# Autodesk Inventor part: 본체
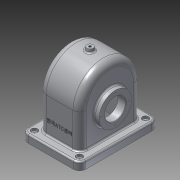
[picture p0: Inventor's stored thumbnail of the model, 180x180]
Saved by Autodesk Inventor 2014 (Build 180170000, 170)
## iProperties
Created: 2016-10
Part Number: 본체
Material: 알루미늄 6061
Document SubType Name: Modeling
Designer: user
Density: 2.71 g/cm^3
Appearance: 알루미늄 - 평지
Mass: 1165.05 g
Surface Area: 1200.06 cm^2
Volume: 429.908 cm^3
Author: user
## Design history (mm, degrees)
sketch "스케치1"
  geometry: L1 (-55, -75)-(55, -75); L2 (55, -75)-(55, 75); L3 (55, 75)-(-55, 75); L4 (-55, 75)-(-55, -75); L5 (-55, -75)-(55, 75); L6 (55, -75)-(-55, 75); 1 further point
  constraints: 12 end point, 2 midpoint, 2 parallel, 1 horizontal, 1 perpendicular
  dimensions: "d0" = 110 distance of L3.end L2.end; "d1" = 150 distance of L2.end L1.end
extrude "돌출1" new body sketch "스케치1" distance "d2" = 15; taper "d3" = 0 deg
fillet "모깎기1" dims "d4" = 12
sketch "스케치2"
  geometry: L1 (0, 0)-(0, 80); L2 (-63, 15)-(63, 15) reference; L3 (-58, 80)-(-58, 15); L4 (58, 80)-(58, 15); A1 r 58 centre (0, 80) between (58, 80) and (-58, 80)
  constraints: 6 end point, 2 perpendicular, 2 point on circle, 2 point on line, 2 tangent, 1 centre point, 1 vertical
  dimensions: "d5" = 80 distance of L1.start L1.end; "d7" = 58 radius of A1
extrude "돌출2" join sketch "스케치2" stored distance "d8" = 77; taper "d9" = 0 deg
sketch "스케치3"
  geometry: L1 (0, 0)-(0, 80); L2 (52, 80)-(52, 0); L3 (-52, 80)-(-52, 0); A1 r 52 centre (0, 80) between (52, 80) and (-52, 80)
  constraints: 6 end point, 2 parallel, 2 point on circle, 2 tangent, 1 centre point, 1 coincident, 1 vertical
  dimensions: "d10" = 80 distance of L1.start L1.end; "d11" = 52 radius of A1
extrude "돌출3" cut sketch "스케치3" stored distance "d13" = 67; taper "d14" = 0 deg
node "작업 평면1"
sketch "스케치4"
  geometry: C1 r 6 at (0, 0); 1 further point
  constraints: 1 centre point, 1 coincident
  dimensions: "d17" = 12 diameter of C1
extrude "돌출4" join sketch "스케치4" stored distance "d18" = 67; taper "d19" = 10 deg
hole "구멍1" diameter "d22" = 4.459; stored, may be unused: countersink angle "d26" = 90 deg, drill point angle "d28" = 0 deg; dims "d23" = 6, "d24" = 4, "d25" = 2, "d27" = 8, "d122" = 10, "d123" = 10
sketch "스케치5"
  geometry: L1 (0, 63)-(0, -63) reference; C1 r 37.5 at (65, 0); A1 r 58 centre (80, 0) between (80, -58) and (80, 58) reference; 1 further point
  constraints: 1 centre point, 1 horizontal alignment
  dimensions: "d86" = 65 distance from line of C1.centre L1; "d87" = 75 diameter of C1
extrude "돌출5" join sketch "스케치5" distance "d31" = 5; taper "d32" = 0 deg
fillet "모깎기2" dims "d66" = 3
fillet "모깎기4" dims "d68" = 13
sketch "스케치10"
  geometry: L1 (-17.5, -80)-(68.5, -80) reference; L2 (-13, 0)-(-13, -65) reference; 2 further points
  constraints: 1 other
  dimensions: "d69" = 40 distance from line of point (25.5, -40) L1; "d71" = 38.5 distance from line of point (25.5, -40) L2
feature "엠보싱1" sketch "스케치10" dims "d0" = 110, "d1" = 150, "d72" = 0.5, "d73" = 0
sketch "스케치11"
  geometry: A1 r 9 centre (-43, -63) between (-52, -63) and (-43, -72) reference; A2 r 9 centre (43, -63) between (43, -72) and (52, -63) reference; A3 r 9 centre (43, 63) between (52, 63) and (43, 72) reference; A4 r 9 centre (-43, 63) between (-43, 72) and (-52, 63) reference; 5 further points
  constraints: 4 coincident
hole "구멍5" sketch "스케치11" at (-43, 63), (43, 63), (43, -63), (-43, -63) diameter "d74" = 5; stored, may be unused: countersink angle "d78" = 90 deg, drill point angle "d80" = 0 deg; dims "d75" = 6, "d76" = 12, "d77" = 5, "d79" = 8
fillet "모깎기5" dims "d81" = 3
fillet "모깎기6" dims "d85" = 8
sketch "스케치12"
  geometry: L1 (0, -63)-(0, 63) reference; C1 r 31 at (-65, 0); A1 r 45 centre (-80, 0) between (-80, 45) and (-80, -45) reference; 1 further point
  constraints: 1 centre point, 1 horizontal alignment
  dimensions: "d88" = 62 diameter of C1; "d89" = 65 distance from line of C1.centre L1
extrude "돌출8" join sketch "스케치12" distance "d90" = 10; taper "d91" = 0 deg
fillet "모깎기7" dims "d92" = 3
sketch "스케치13"
  geometry: C1 r 37.5 at (0, 0) reference; A1 r 29 centre (0, 0) between (0, 29) and (29, 0); 3 further points
  constraints: 4 point on circle, 1 centre point, 1 coincident
  dimensions: "d93" = 58 diameter of A1
hole "구멍6" sketch "스케치13" at (0, 29), (29, 0), (0, -29), (-29, 0) diameter "d94" = 2.459; stored, may be unused: countersink angle "d98" = 90 deg, drill point angle "d100" = 118 deg; dims "d95" = 6, "d96" = 4, "d97" = 2, "d99" = 8
sketch "스케치14"
  geometry: C1 r 31 at (0, 0) reference; A1 r 26.5 centre (0, 0) between (0, 26.5) and (26.5, 0); 3 further points
  constraints: 4 point on circle, 1 centre point, 1 coincident
  dimensions: "d101" = 53 diameter of A1
hole "구멍7" sketch "스케치14" at (0, 26.5), (26.5, 0), (0, -26.5), (-26.5, 0) diameter "d102" = 2.459; stored, may be unused: countersink angle "d106" = 90 deg, drill point angle "d108" = 118 deg; dims "d103" = 6, "d104" = 4, "d105" = 2, "d107" = 8
sketch "스케치15"
  geometry: C1 r 37.5 at (0, 0) reference; C2 r 20 at (0, 0); 1 further point
  constraints: 1 centre point, 1 coincident
  dimensions: "d109" = 40 diameter of C2
extrude "돌출9" cut sketch "스케치15" distance "d110" = 24; taper "d111" = 0 deg
sketch "스케치16"
  geometry: C1 r 31 at (0, 0) reference; C2 r 20 at (0, 0); 1 further point
  constraints: 1 centre point, 1 coincident
  dimensions: "d112" = 40 diameter of C2
extrude "돌출10" cut sketch "스케치16" distance "d113" = 15; taper "d114" = 0 deg
chamfer "모따기2" distance "d115" = 1; stored, may be unused: second distance "d116" = 2, angle "d117" = 45 deg
node "작업 평면2"
sketch "스케치19"
  geometry: C1 r 28 at (0, 0); 1 further point
  constraints: 1 centre point
  dimensions: "d121" = 56 diameter of C1
extrude "돌출11" join sketch "스케치19" distance "d124" = 15; taper "d125" = 40 deg
sketch "스케치20"
  geometry: C1 r 21 at (0, 0) reference; C2 r 20 at (0, 0); 1 further point
  constraints: 1 centre point, 1 coincident
  dimensions: "d126" = 40 diameter of C2
extrude "돌출12" cut sketch "스케치20" distance "d127" = 24; taper "d128" = 0 deg
node "솔리드1"
other parameters: "d12" = 67, "d15" = -144, "d120" = -24
